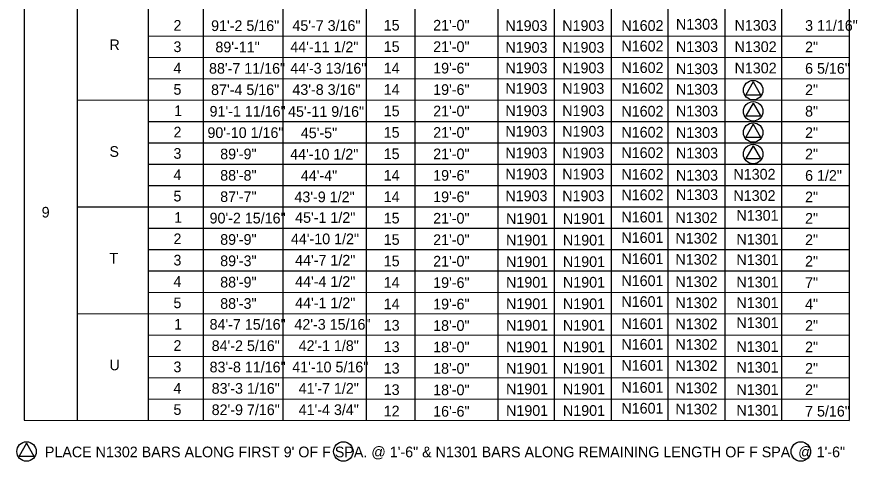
# Model space of a CAD drawing. Extents: x -50.5 to -14.4, y -5.1 to 16.9.
# Drawn here: x -35.75 to -25.91, y 6.15 to 11.35 of the extents above; entities that cross this region are included whole.
import ezdxf

# ---------------------------------------------------------------- set-up
doc = ezdxf.new("R2010")
doc.units = 0
for name, color, linetype in [('BR_AUTO DIMENSION', 7, 'Continuous'), ('BR_BORDER LINES', 7, 'Continuous'), ('BR_TABLE LINES', 7, 'Continuous'), ('BR_TEXT', 7, 'Continuous')]:
    doc.layers.add(name, color=color, linetype=linetype)

msp = doc.modelspace()

# ---------------------------------------------------------------- linework, layer by layer
at = {"layer": 'BR_AUTO DIMENSION'}
for p, q in [((-27.1318, 10.5901), (-27.2187, 10.4407)), ((-27.1318, 10.5901), (-27.0448, 10.4407)), ((-27.2187, 10.4407), (-27.0448, 10.4407)), ((-27.1318, 10.3419), (-27.2187, 10.1924)), ((-27.1318, 10.3419), (-27.0448, 10.1924)), ((-27.2187, 10.1924), (-27.0448, 10.1924)), ((-27.1318, 10.0937), (-27.2187, 9.9442)), ((-27.1318, 10.0937), (-27.0448, 9.9442)), ((-27.2187, 9.9442), (-27.0448, 9.9442)), ((-27.1318, 9.8415), (-27.2187, 9.6921)), ((-27.1318, 9.8415), (-27.0448, 9.6921)), ((-27.2187, 9.6921), (-27.0448, 9.6921)), ((-35.6388, 6.3575), (-35.7258, 6.2081)), ((-35.6388, 6.3575), (-35.5519, 6.2081)), ((-35.7258, 6.2081), (-35.5519, 6.2081))]:
    msp.add_line(p, q, dxfattribs=at)
for centre in [(-27.1318, 10.4937), (-27.1318, 10.2455), (-27.1318, 9.9972), (-27.1318, 9.7451), (-35.6388, 6.2611), (-31.9297, 6.2611), (-26.5743, 6.2611)]:
    msp.add_circle(centre, 0.1139, dxfattribs=at)
at = {"layer": 'BR_BORDER LINES'}
for p, q in [((-35.6657, 16.4338), (-35.6657, 6.6283)), ((-26.0058, 16.4302), (-26.0058, 6.6247)), ((-35.6657, 6.6283), (-26.0058, 6.6251))]:
    msp.add_line(p, q, dxfattribs=at)
at = {"layer": 'BR_TABLE LINES'}
for p, q in [((-35.0452, 15.7743), (-35.0452, 6.6283)), ((-34.2134, 15.7736), (-34.2134, 6.6283)), ((-33.5724, 15.7728), (-33.5724, 6.6283)), ((-32.6394, 15.772), (-32.6394, 6.6283)), ((-31.663, 15.7712), (-31.663, 6.6247)), ((-31.0915, 15.7712), (-31.0915, 6.6247)), ((-30.1219, 15.7712), (-30.1219, 6.6247)), ((-29.4619, 15.7712), (-29.4619, 6.6247)), ((-28.7959, 15.7712), (-28.7959, 6.6247)), ((-28.1299, 15.7712), (-28.1299, 6.6247)), ((-27.4639, 15.7712), (-27.4639, 6.6247)), ((-26.7979, 15.7712), (-26.7979, 6.6247)), ((-26.0058, 15.7712), (-26.0058, 6.6247)), ((-34.2134, 11.1283), (-26.0058, 11.1252)), ((-34.2134, 10.8783), (-26.0058, 10.8752)), ((-34.2134, 10.6283), (-26.0058, 10.6252)), ((-35.0452, 10.3783), (-26.0058, 10.3752)), ((-34.2134, 10.1283), (-26.0058, 10.1252)), ((-34.2134, 9.8783), (-26.0058, 9.8752)), ((-34.2134, 9.6283), (-26.0058, 9.6252)), ((-34.2134, 9.3783), (-26.0058, 9.3752)), ((-35.0452, 9.1283), (-26.0058, 9.1252)), ((-34.2134, 8.8783), (-26.0058, 8.8752)), ((-34.2134, 8.6283), (-26.0058, 8.6252)), ((-34.2134, 8.3783), (-26.0058, 8.3752)), ((-34.2134, 8.1283), (-26.0058, 8.1252)), ((-35.0452, 7.8783), (-26.0058, 7.8752)), ((-34.2134, 7.6283), (-26.0058, 7.6252)), ((-34.2134, 7.3783), (-26.0058, 7.3752)), ((-34.2134, 7.1283), (-26.0058, 7.1252)), ((-34.2134, 6.8783), (-26.0058, 6.8752))]:
    msp.add_line(p, q, dxfattribs=at)

# ---------------------------------------------------------------- texts
at = {"layer": 'BR_TEXT'}
for s, p in [('2', (-33.9184, 11.1897)), ('91\'-2 5/16"', (-33.4778, 11.1863)), ('45\'-7 3/16"', (-32.5261, 11.1877)), ('15', (-31.4569, 11.1922)), ('21\'-0"', (-30.8778, 11.1916)), ('N1303', (-28.0352, 11.2036)), ('N1303 ', (-27.3494, 11.1903)), ('3 11/16"', (-26.5235, 11.1885)), ('N1903', (-30.0325, 11.1867)), ('N1903', (-29.3665, 11.1867)), ('N1602', (-28.674, 11.1878)), ('3', (-33.9184, 10.9397)), ('89\'-11"', (-33.4274, 10.9363)), ('44\'-11 1/2"', (-32.5505, 10.9377)), ('15', (-31.4569, 10.9411)), ('21\'-0"', (-30.8778, 10.9403)), ('N1903', (-30.0325, 10.9323)), ('N1903', (-29.3665, 10.9323)), ('N1602', (-28.674, 10.9472)), ('N1303', (-28.0352, 10.9404)), ('N1302', (-27.3494, 10.9403)), ('2"', (-26.5235, 10.9375)), ('4', (-33.9184, 10.6897)), ('88\'-7 11/16"', (-33.5022, 10.6863)), ('44\'-3 13/16"', (-32.5505, 10.6877)), ('14', (-31.4569, 10.69)), ('19\'-6"', (-30.8778, 10.6891)), ('N1903', (-30.0325, 10.6917)), ('N1903', (-29.3665, 10.6917)), ('N1602', (-28.674, 10.6945)), ('N1303', (-28.0352, 10.6811)), ('N1302', (-27.3494, 10.6903)), ('6 5/16"', (-26.5235, 10.6865)), ('5', (-33.9184, 10.4397)), ('87\'-4 5/16"', (-33.4778, 10.4363)), ('43\'-8 3/16"', (-32.5261, 10.4377)), ('14', (-31.4569, 10.4388)), ('19\'-6"', (-30.8778, 10.4378)), ('N1903', (-30.0325, 10.451)), ('N1903', (-29.3665, 10.451)), ('N1602', (-28.674, 10.4539)), ('N1303', (-28.0352, 10.4415)), ('2"', (-26.5235, 10.4355)), ('1', (-33.9101, 10.1897)), ('91\'-1 11/16"', (-33.4958, 10.1833)), ('45\'-11 9/16"', (-32.577, 10.1808)), ('15', (-31.4569, 10.1877)), ('21\'-0"', (-30.8778, 10.1866)), ('N1903', (-30.0325, 10.1898)), ('N1903', (-29.3665, 10.1898)), ('N1602', (-28.674, 10.1843)), ('N1303', (-28.0352, 10.1861)), ('8"', (-26.5235, 10.1845)), ('2', (-33.9184, 9.9397)), ('90\'-10 1/16"', (-33.521, 9.9333)), ('45\'-5"', (-32.4274, 9.9308)), ('15', (-31.4569, 9.9366)), ('21\'-0"', (-30.8778, 9.9353)), ('N1903', (-30.0325, 9.9492)), ('N1903', (-29.3665, 9.9492)), ('N1602', (-28.674, 9.9385)), ('N1303', (-28.0352, 9.9347)), ('2"', (-26.5235, 9.9335)), ('3', (-33.9184, 9.6897)), ('89\'-9"', (-33.3714, 9.6833)), ('44\'-10 1/2"', (-32.5518, 9.6808)), ('15', (-31.4569, 9.6855)), ('21\'-0"', (-30.8778, 9.6841)), ('N1903', (-30.0325, 9.6948)), ('N1903', (-29.3665, 9.6948)), ('N1602', (-28.674, 9.6979)), ('N1303', (-28.0352, 9.694)), ('2"', (-26.5235, 9.6825)), ('4', (-33.9184, 9.4397)), ('88\'-8"', (-33.3714, 9.4333)), ('44\'-4"', (-32.4274, 9.4308)), ('14', (-31.4569, 9.4343)), ('19\'-6"', (-30.8778, 9.4328)), ('N1903', (-30.0325, 9.4473)), ('N1903', (-29.3665, 9.4473)), ('N1602', (-28.674, 9.4452)), ('N1303', (-28.0352, 9.4347)), ('N1302', (-27.3625, 9.4464)), ('6 1/2"', (-26.5235, 9.4315)), ('5', (-33.9184, 9.1897)), ('87\'-7"', (-33.3714, 9.1833)), ('43\'-9 1/2"', (-32.5022, 9.1808)), ('14', (-31.4569, 9.1832)), ('19\'-6"', (-30.8778, 9.1816)), ('N1903', (-30.0325, 9.1929)), ('N1903', (-29.3665, 9.1929)), ('N1602', (-28.674, 9.2046)), ('N1303', (-28.0352, 9.2069)), ('N1302', (-27.3625, 9.1964)), ('2"', (-26.5235, 9.1805)), ('1', (-33.9101, 8.9397)), ('90\'-2 15/16"', (-33.4958, 8.932)), ('45\'-1 1/2"', (-32.494, 8.939)), ('15', (-31.4569, 8.9321)), ('21\'-0"', (-30.8778, 8.9303)), ('N1901', (-30.0243, 8.927)), ('N1901', (-29.3583, 8.927)), ('N1601', (-28.6742, 8.9436)), ('N1302', (-28.0413, 8.9369)), ('N1301', (-27.327, 8.9644)), ('2"', (-26.5235, 8.9295)), ('2', (-33.9184, 8.6897)), ('89\'-9"', (-33.3714, 8.682)), ('44\'-10 1/2"', (-32.5436, 8.689)), ('15', (-31.4569, 8.681)), ('21\'-0"', (-30.8778, 8.6791)), ('N1901', (-30.0243, 8.6743)), ('N1901', (-29.3583, 8.6743)), ('N1601', (-28.6742, 8.7036)), ('N1302', (-28.0413, 8.6962)), ('N1301', (-27.327, 8.6855)), ('2"', (-26.5235, 8.6785)), ('3', (-33.9184, 8.4397)), ('44\'-7 1/2"', (-32.494, 8.439)), ('N1601', (-28.6742, 8.4561)), ('N1302', (-28.0413, 8.4487)), ('N1301', (-27.327, 8.4444)), ('89\'-3"', (-33.3714, 8.432)), ('15', (-31.4569, 8.4298)), ('21\'-0"', (-30.8778, 8.4278)), ('N1901', (-30.0243, 8.4216)), ('N1901', (-29.3583, 8.4216)), ('2"', (-26.5235, 8.4275)), ('4', (-33.9184, 8.1897)), ('88\'-9"', (-33.3714, 8.182)), ('44\'-4 1/2"', (-32.494, 8.189)), ('14', (-31.4569, 8.1787)), ('19\'-6"', (-30.8778, 8.1766)), ('N1901', (-30.0243, 8.181)), ('N1901', (-29.3583, 8.181)), ('N1601', (-28.6742, 8.1977)), ('N1302', (-28.0413, 8.1875)), ('N1301', (-27.327, 8.1826)), ('7"', (-26.5235, 8.1765)), ('44\'-1 1/2"', (-32.494, 7.939)), ('N1601', (-28.6742, 7.9543)), ('5', (-33.9184, 7.9397)), ('88\'-3"', (-33.3714, 7.932)), ('14', (-31.4569, 7.9276)), ('19\'-6"', (-30.8778, 7.9253)), ('N1901', (-30.0243, 7.9284)), ('N1901', (-29.3583, 7.9284)), ('N1302', (-28.0413, 7.94)), ('N1301', (-27.327, 7.9408)), ('4"', (-26.5235, 7.9255)), ('1', (-33.9101, 7.6897)), ('84\'-7 15/16"', (-33.4958, 7.6876)), ('42\'-3 15/16"', (-32.5024, 7.6878)), ('13', (-31.4569, 7.6765)), ('18\'-0"', (-30.8778, 7.6741)), ('N1901', (-30.0243, 7.677)), ('N1901', (-29.3583, 7.677)), ('N1601', (-28.6742, 7.6943)), ('N1302', (-28.0413, 7.6925)), ('N1301', (-27.327, 7.7061)), ('2"', (-26.5235, 7.6745)), ('N1601', (-28.6742, 7.4543)), ('N1302', (-28.0413, 7.4518)), ('2', (-33.9184, 7.4397)), ('84\'-2 5/16"', (-33.4714, 7.4376)), ('42\'-1 1/8"', (-32.4528, 7.4378)), ('13', (-31.4569, 7.4253)), ('18\'-0"', (-30.8778, 7.4228)), ('N1901', (-30.0243, 7.4243)), ('N1901', (-29.3583, 7.4243)), ('N1301', (-27.327, 7.4271)), ('2"', (-26.5235, 7.4235)), ('3', (-33.9184, 7.1897)), ('83\'-8 11/16"', (-33.4958, 7.1876)), ('41\'-10 5/16"', (-32.5276, 7.1878)), ('13', (-31.4569, 7.1742)), ('18\'-0"', (-30.8778, 7.1716)), ('N1901', (-30.0243, 7.1716)), ('N1901', (-29.3583, 7.1716)), ('N1601', (-28.6742, 7.2068)), ('N1302', (-28.0413, 7.2043)), ('N1301', (-27.327, 7.186)), ('2"', (-26.5235, 7.1725)), ('4', (-33.9184, 6.9397)), ('83\'-3 1/16"', (-33.4714, 6.9376)), ('41\'-7 1/2"', (-32.4528, 6.9378)), ('13', (-31.4569, 6.9231)), ('18\'-0"', (-30.8778, 6.9203)), ('N1901', (-30.0243, 6.931)), ('N1901', (-29.3583, 6.931)), ('N1601', (-28.6742, 6.9484)), ('N1302', (-28.0413, 6.9431)), ('N1301', (-27.327, 6.9243)), ('2"', (-26.5235, 6.9215)), ('5', (-33.9184, 6.6897)), ('82\'-9 7/16"', (-33.4714, 6.6876)), ('41\'-4 3/4"', (-32.4528, 6.6878)), ('12', (-31.4569, 6.672)), ('16\'-6"', (-30.8778, 6.6691)), ('N1901', (-30.0243, 6.6784)), ('N1901', (-29.3583, 6.6784)), ('N1601', (-28.6742, 6.705)), ('N1302', (-28.0413, 6.6956)), ('N1301', (-27.327, 6.6824)), ('7 5/16"', (-26.5235, 6.6705))]:
    msp.add_text(s, height=0.125, dxfattribs=at).set_placement(p)
for s, p in [('R', (-34.668, 10.9624)), ('S', (-34.668, 9.7124)), ('9', (-35.4615, 9.0013)), ('T', (-34.668, 8.4624)), ('U', (-34.668, 7.2124)), ('PLACE N1302 BARS ALONG FIRST 9\' OF F SPA. @ 1\'-6" & N1301 BARS ALONG REMAINING LENGTH OF F SPA. @ 1\'-6"', (-35.4242, 6.193))]:
    msp.add_text(s, height=0.125, rotation=360, dxfattribs=at).set_placement(p)

doc.saveas('drawing.dxf')
